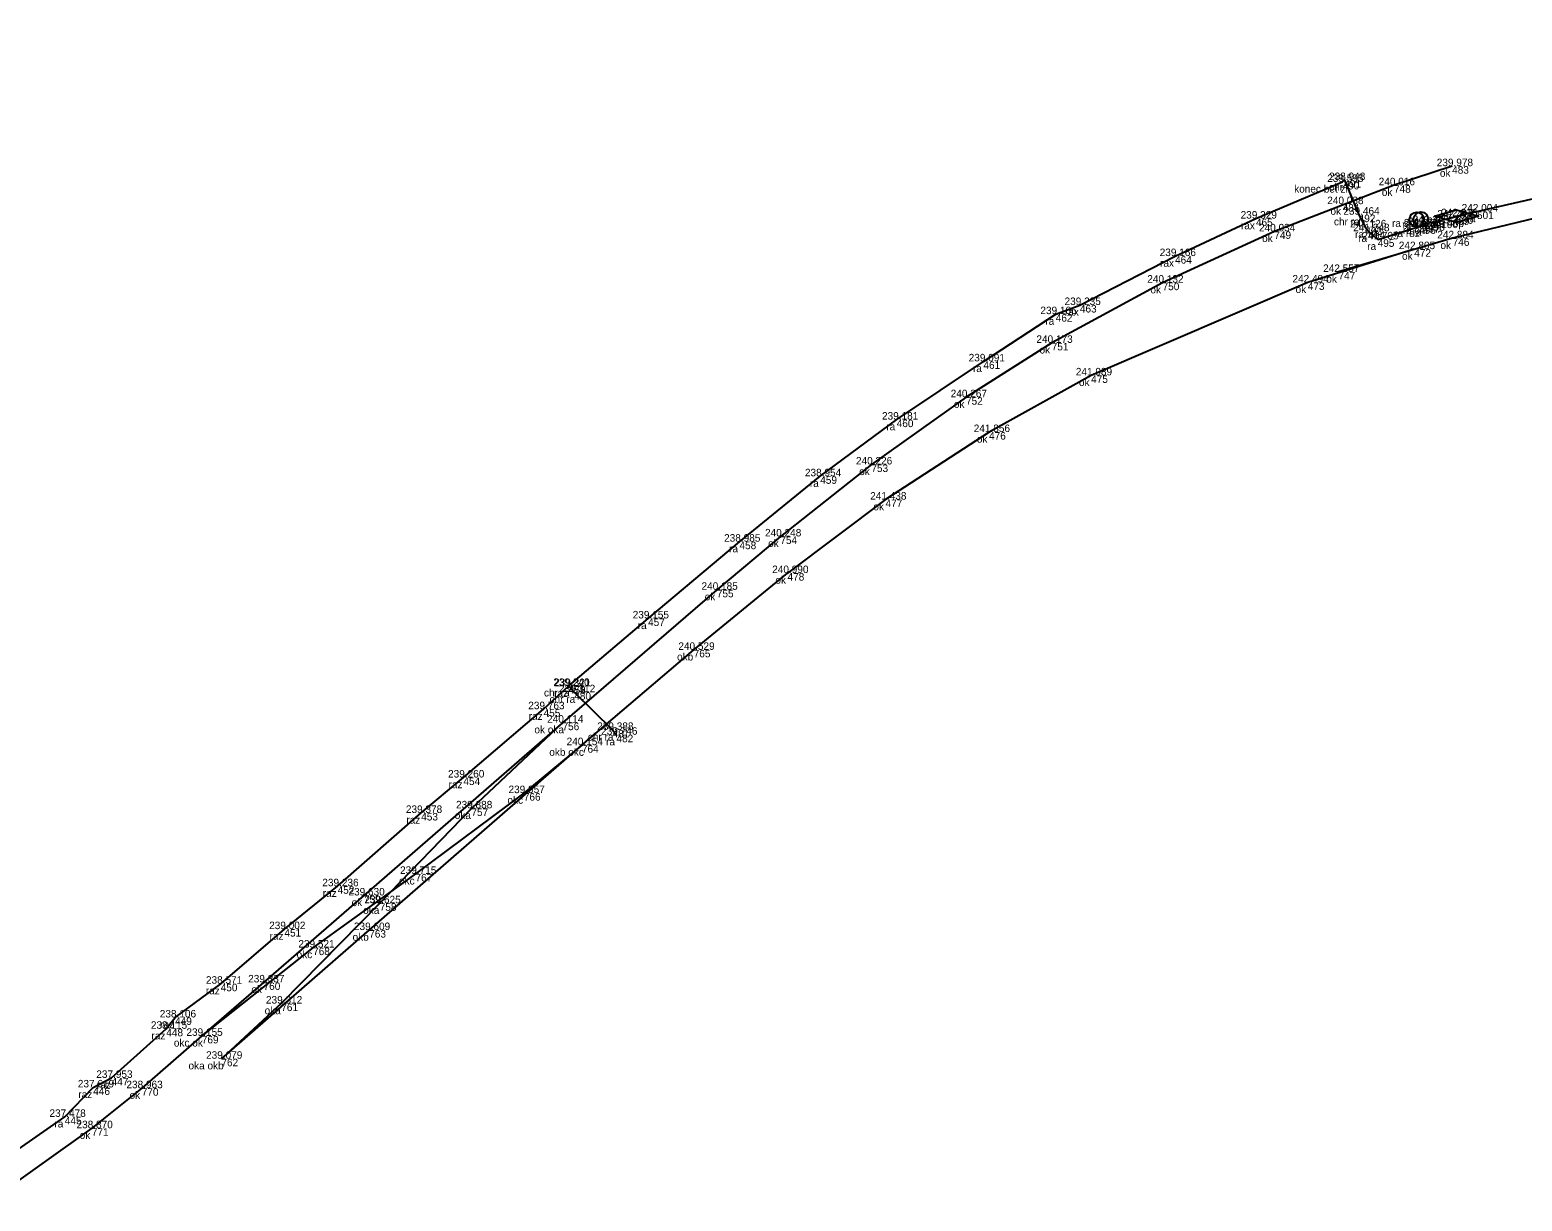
# Model space of a CAD drawing. Extents: x -759609 to -758899, y -1026011 to -1025762.
# Drawn here: x -759291 to -759052.4, y -1025950.3 to -1025763 of the extents above; entities that cross this region are included whole.
import ezdxf

# ---------------------------------------------------------------- set-up
doc = ezdxf.new("R2010")
doc.units = 0
for name, color, linetype in [('Vrstva 1', 7, 'Continuous'), ('Vrstva 28', 7, 'Continuous'), ('Vrstva 33', 7, 'Continuous'), ('Vrstva 35', 7, 'Continuous'), ('Vrstva 60', 7, 'Continuous'), ('Vrstva 61', 7, 'Continuous'), ('Vrstva 62', 7, 'Continuous')]:
    doc.layers.add(name, color=color, linetype=linetype)

msp = doc.modelspace()

# ---------------------------------------------------------------- linework, layer by layer
at = {"layer": 'Vrstva 1'}
for points in [[(-758902.55, -1025766.11), (-758912.99, -1025767.18), (-758931.03, -1025769.64), (-758951.6, -1025773.2), (-758974.19, -1025777.6), (-759000.96, -1025782.89), (-759025.45, -1025787.76), (-759044.35, -1025791.72), (-759063.54, -1025796.36), (-759081.79, -1025801.74)], [(-759063.62, -1025784.83), (-759072.91, -1025787.88), (-759092.04, -1025795.25), (-759109.9, -1025803.45), (-759127.62, -1025813.07), (-759141.32, -1025821.76), (-759156.45, -1025832.51), (-759171, -1025844.01), (-759181.15, -1025852.54), (-759205.82, -1025873.78), (-759237.58, -1025901.4), (-759253.6, -1025915.3), (-759263.47, -1025923.84), (-759273.07, -1025932.21), (-759281.05, -1025938.61), (-759297.45, -1025950.26)], [(-759069.68, -1025798.09), (-759086.69, -1025803.42), (-759121.32, -1025818.27), (-759137.64, -1025827.33), (-759154.19, -1025838.13), (-759169.85, -1025849.87)], [(-759260.34, -1025927.5), (-759236.71, -1025906.93), (-759202.71, -1025877.38), (-759184.85, -1025862.14), (-759169.85, -1025849.87)], [(-759205.82, -1025873.78), (-759220.38, -1025887.48), (-759235.03, -1025902.65), (-759250.77, -1025918.68), (-759260.34, -1025927.5)], [(-759202.71, -1025877.38), (-759212, -1025885.04), (-759229.32, -1025897.95), (-759245.68, -1025909.73), (-759263.47, -1025923.84)]]:
    msp.add_lwpolyline(points, dxfattribs=at)
at = {"layer": 'Vrstva 28'}
for points in [[(-759063.54, -1025793.03), (-759062.92, -1025792.84), (-759059.65, -1025792.08), (-759043.8, -1025788.44), (-759029.74, -1025785.63), (-759012.27, -1025782.09), (-759002.49, -1025780.17), (-759001.63, -1025779.68), (-758999.1, -1025779.52), (-758985.35, -1025776.25), (-758985.36, -1025776.26), (-758959.77, -1025770.53), (-758951.22, -1025768.17), (-758944.78, -1025766.82), (-758944.75, -1025766.82), (-758934.78, -1025765.55), (-758913.94, -1025763.04), (-758913.31, -1025763.73)], [(-759204.83, -1025867.9), (-759192.14, -1025857.12), (-759177.53, -1025844.85), (-759164.62, -1025834.4), (-759152.4, -1025825.34), (-759138.54, -1025816.03), (-759126.98, -1025808.48), (-759123.12, -1025807.02), (-759107.91, -1025799.2), (-759094.98, -1025793.21), (-759081.13, -1025787.35), (-759080.85, -1025787.05), (-759078.56, -1025792.58), (-759077.49, -1025794.61), (-759076.98, -1025795.23), (-759075.52, -1025796.53), (-759068.91, -1025794.46), (-759068.28, -1025794.23), (-759067.47, -1025793.95)], [(-759067.47, -1025793.95), (-759063.54, -1025793.03)], [(-759299.69, -1025946.77), (-759285.37, -1025936.79), (-759280.83, -1025932.08), (-759277.89, -1025930.56), (-759269.15, -1025922.71), (-759267.74, -1025920.9), (-759260.45, -1025915.51), (-759250.26, -1025906.78), (-759241.76, -1025899.93), (-759228.4, -1025888.21), (-759221.66, -1025882.55), (-759208.84, -1025871.63), (-759204.83, -1025867.9)], [(-759204.83, -1025867.9), (-759204.8, -1025867.96), (-759203.94, -1025868.92), (-759197.82, -1025874.94), (-759197.19, -1025875.71)]]:
    msp.add_lwpolyline(points, dxfattribs=at)
at = {"layer": 'Vrstva 33'}
for p, q in [((-759065.47, -1025793.13), (-759064.67, -1025792.33)), ((-759063.4, -1025793.71), (-759061.8, -1025792.15)), ((-759060.02, -1025793.02), (-759059.72, -1025792.73))]:
    msp.add_line(p, q, dxfattribs=at)
msp.add_lwpolyline([(-759066.45, -1025792.84), (-759062.92, -1025791.82), (-759059.4, -1025792.84), (-759062.92, -1025793.85)], close=True, dxfattribs=at)
for centre in [(-759069.27, -1025793.34), (-759068.62, -1025793.32)]:
    msp.add_circle(centre, 1.17, dxfattribs=at)
at = {"layer": 'Vrstva 35'}
for points in [[(-759080.85, -1025787.05), (-759078.56, -1025792.58)], [(-759067.47, -1025793.95), (-759063.54, -1025793.03)], [(-759204.8, -1025867.96), (-759203.94, -1025868.92), (-759197.82, -1025874.94)]]:
    msp.add_lwpolyline(points, dxfattribs=at)
at = {"layer": 'Vrstva 60'}
for p, q in [((-759063.62, -1025784.83), (-759063.62, -1025784.83)), ((-759081.13, -1025787.35), (-759081.13, -1025787.35)), ((-759080.85, -1025787.05), (-759080.85, -1025787.05)), ((-759072.91, -1025787.88), (-759072.91, -1025787.88)), ((-759094.98, -1025793.21), (-759094.98, -1025793.21)), ((-759081.12, -1025790.9), (-759081.12, -1025790.9)), ((-759078.56, -1025792.58), (-759078.56, -1025792.58)), ((-759063.54, -1025793.03), (-759063.54, -1025793.03)), ((-759062.92, -1025792.84), (-759062.92, -1025792.84)), ((-759059.65, -1025792.08), (-759059.65, -1025792.08)), ((-759092.04, -1025795.25), (-759092.04, -1025795.25)), ((-759077.49, -1025794.61), (-759077.49, -1025794.61)), ((-759076.98, -1025795.23), (-759076.98, -1025795.23)), ((-759068.91, -1025794.46), (-759068.91, -1025794.46)), ((-759068.28, -1025794.23), (-759068.28, -1025794.23)), ((-759067.47, -1025793.95), (-759067.47, -1025793.95)), ((-759075.52, -1025796.53), (-759075.52, -1025796.53)), ((-759063.54, -1025796.36), (-759063.54, -1025796.36)), ((-759107.91, -1025799.2), (-759107.91, -1025799.2)), ((-759069.68, -1025798.09), (-759069.68, -1025798.09)), ((-759081.79, -1025801.74), (-759081.79, -1025801.74)), ((-759109.9, -1025803.45), (-759109.9, -1025803.45)), ((-759086.69, -1025803.42), (-759086.69, -1025803.42)), ((-759123.12, -1025807.02), (-759123.12, -1025807.02)), ((-759126.98, -1025808.48), (-759126.98, -1025808.48)), ((-759127.62, -1025813.07), (-759127.62, -1025813.07)), ((-759138.54, -1025816.03), (-759138.54, -1025816.03)), ((-759121.32, -1025818.27), (-759121.32, -1025818.27)), ((-759141.32, -1025821.76), (-759141.32, -1025821.76)), ((-759152.4, -1025825.34), (-759152.4, -1025825.34)), ((-759137.64, -1025827.33), (-759137.64, -1025827.33)), ((-759156.45, -1025832.51), (-759156.45, -1025832.51)), ((-759164.62, -1025834.4), (-759164.62, -1025834.4)), ((-759154.19, -1025838.13), (-759154.19, -1025838.13)), ((-759177.53, -1025844.85), (-759177.53, -1025844.85)), ((-759171, -1025844.01), (-759171, -1025844.01)), ((-759169.85, -1025849.87), (-759169.85, -1025849.87)), ((-759181.15, -1025852.54), (-759181.15, -1025852.54)), ((-759192.14, -1025857.12), (-759192.14, -1025857.12)), ((-759184.85, -1025862.14), (-759184.85, -1025862.14)), ((-759204.83, -1025867.9), (-759204.83, -1025867.9)), ((-759204.8, -1025867.96), (-759204.8, -1025867.96)), ((-759203.94, -1025868.92), (-759203.94, -1025868.92)), ((-759208.84, -1025871.63), (-759208.84, -1025871.63)), ((-759205.82, -1025873.78), (-759205.82, -1025873.78)), ((-759197.82, -1025874.94), (-759197.82, -1025874.94)), ((-759197.19, -1025875.71), (-759197.19, -1025875.71)), ((-759202.71, -1025877.38), (-759202.71, -1025877.38)), ((-759221.66, -1025882.55), (-759221.66, -1025882.55)), ((-759212, -1025885.04), (-759212, -1025885.04)), ((-759228.4, -1025888.21), (-759228.4, -1025888.21)), ((-759220.38, -1025887.48), (-759220.38, -1025887.48)), ((-759229.32, -1025897.95), (-759229.32, -1025897.95)), ((-759241.76, -1025899.93), (-759241.76, -1025899.93)), ((-759237.58, -1025901.4), (-759237.58, -1025901.4)), ((-759235.03, -1025902.65), (-759235.03, -1025902.65)), ((-759250.26, -1025906.78), (-759250.26, -1025906.78)), ((-759236.71, -1025906.93), (-759236.71, -1025906.93)), ((-759245.68, -1025909.73), (-759245.68, -1025909.73)), ((-759260.45, -1025915.51), (-759260.45, -1025915.51)), ((-759253.6, -1025915.3), (-759253.6, -1025915.3)), ((-759250.77, -1025918.68), (-759250.77, -1025918.68)), ((-759267.74, -1025920.9), (-759267.74, -1025920.9)), ((-759269.15, -1025922.71), (-759269.15, -1025922.71)), ((-759263.47, -1025923.84), (-759263.47, -1025923.84)), ((-759260.34, -1025927.5), (-759260.34, -1025927.5)), ((-759277.89, -1025930.56), (-759277.89, -1025930.56)), ((-759280.83, -1025932.08), (-759280.83, -1025932.08)), ((-759273.07, -1025932.21), (-759273.07, -1025932.21)), ((-759285.37, -1025936.79), (-759285.37, -1025936.79)), ((-759281.05, -1025938.61), (-759281.05, -1025938.61))]:
    msp.add_line(p, q, dxfattribs=at)

# ---------------------------------------------------------------- texts
for s, p in [('483', (-759063.62, -1025786.03)), ('490', (-759081.13, -1025788.55)), ('491', (-759080.85, -1025788.25)), ('748', (-759072.91, -1025789.08)), ('465', (-759094.98, -1025794.41)), ('484', (-759081.12, -1025792.1)), ('492', (-759078.56, -1025793.78)), ('499', (-759063.54, -1025794.23)), ('500', (-759062.92, -1025794.04)), ('501', (-759059.65, -1025793.28)), ('749', (-759092.04, -1025796.45)), ('493', (-759077.49, -1025795.81)), ('494', (-759076.98, -1025796.43)), ('496', (-759068.91, -1025795.66)), ('497', (-759068.28, -1025795.43)), ('498', (-759067.47, -1025795.15)), ('495', (-759075.52, -1025797.72)), ('746', (-759063.54, -1025797.56)), ('464', (-759107.91, -1025800.4)), ('472', (-759069.68, -1025799.29)), ('747', (-759081.79, -1025802.94)), ('750', (-759109.9, -1025804.65)), ('473', (-759086.69, -1025804.61)), ('463', (-759123.12, -1025808.22)), ('462', (-759126.98, -1025809.68)), ('751', (-759127.62, -1025814.27)), ('461', (-759138.54, -1025817.23)), ('475', (-759121.32, -1025819.47)), ('752', (-759141.32, -1025822.96)), ('460', (-759152.4, -1025826.54)), ('476', (-759137.64, -1025828.53)), ('753', (-759156.45, -1025833.71)), ('459', (-759164.62, -1025835.6)), ('477', (-759154.19, -1025839.33)), ('458', (-759177.53, -1025846.05)), ('754', (-759171, -1025845.21)), ('478', (-759169.85, -1025851.07)), ('755', (-759181.15, -1025853.74)), ('457', (-759192.14, -1025858.32)), ('765', (-759184.85, -1025863.34)), ('479', (-759204.83, -1025869.09)), ('456', (-759204.8, -1025869.16)), ('480', (-759203.94, -1025870.12)), ('455', (-759208.84, -1025872.83)), ('756', (-759205.82, -1025874.98)), ('481', (-759197.82, -1025876.14)), ('482', (-759197.19, -1025876.91)), ('764', (-759202.71, -1025878.58)), ('454', (-759221.66, -1025883.75)), ('766', (-759212, -1025886.24)), ('453', (-759228.4, -1025889.41)), ('757', (-759220.38, -1025888.69)), ('767', (-759229.32, -1025899.15)), ('452', (-759241.76, -1025901.13)), ('759', (-759237.58, -1025902.6)), ('758', (-759235.03, -1025903.85)), ('451', (-759250.26, -1025907.97)), ('763', (-759236.71, -1025908.13)), ('768', (-759245.68, -1025910.93)), ('450', (-759260.45, -1025916.71)), ('760', (-759253.6, -1025916.5)), ('761', (-759250.77, -1025919.88)), ('449', (-759267.74, -1025922.09)), ('448', (-759269.15, -1025923.91)), ('769', (-759263.47, -1025925.05)), ('762', (-759260.34, -1025928.7)), ('447', (-759277.89, -1025931.76)), ('446', (-759280.83, -1025933.28)), ('770', (-759273.07, -1025933.41)), ('445', (-759285.37, -1025937.98)), ('771', (-759281.05, -1025939.81))]:
    msp.add_text(s, height=1.2, dxfattribs=at).set_placement(p)
at = {"layer": 'Vrstva 61'}
for s, p in [('239.978', (-759066.08, -1025784.83)), ('238.948', (-759083.3, -1025787.05)), ('239.595', (-759083.59, -1025787.35)), ('240.016', (-759075.36, -1025787.88)), ('240.038', (-759083.58, -1025790.9)), ('239.329', (-759097.43, -1025793.21)), ('239.464', (-759081.01, -1025792.58)), ('241.852', (-759071.35, -1025794.46)), ('242.268', (-759070.73, -1025794.23)), ('242.373', (-759069.92, -1025793.95)), ('242.414', (-759065.99, -1025793.03)), ('242.216', (-759065.38, -1025792.84)), ('242.004', (-759062.1, -1025792.08)), ('240.034', (-759094.49, -1025795.25)), ('241.126', (-759079.94, -1025794.61)), ('241.248', (-759079.43, -1025795.23)), ('241.705', (-759077.98, -1025796.53)), ('242.884', (-759065.99, -1025796.36)), ('239.166', (-759110.37, -1025799.2)), ('242.805', (-759072.14, -1025798.09)), ('240.132', (-759112.35, -1025803.45)), ('242.494', (-759089.14, -1025803.42)), ('242.557', (-759084.24, -1025801.74)), ('239.106', (-759129.43, -1025808.48)), ('239.235', (-759125.57, -1025807.02)), ('240.173', (-759130.07, -1025813.07)), ('239.091', (-759140.9, -1025816.03)), ('241.989', (-759123.77, -1025818.27)), ('240.267', (-759143.77, -1025821.76)), ('239.181', (-759154.75, -1025825.34)), ('241.856', (-759140.09, -1025827.33)), ('240.226', (-759158.91, -1025832.51)), ('238.954', (-759167.07, -1025834.4)), ('241.438', (-759156.64, -1025838.13)), ('240.248', (-759173.45, -1025844.01)), ('238.985', (-759179.99, -1025844.85)), ('240.990', (-759172.3, -1025849.87)), ('240.185', (-759183.6, -1025852.54)), ('239.155', (-759194.6, -1025857.12)), ('240.529', (-759187.3, -1025862.14)), ('239.240', (-759207.28, -1025867.9)), ('239.321', (-759207.16, -1025867.96)), ('239.312', (-759206.39, -1025868.92)), ('239.763', (-759211.29, -1025871.63)), ('240.114', (-759208.27, -1025873.78)), ('239.388', (-759200.27, -1025874.94)), ('240.154', (-759205.16, -1025877.38)), ('239.746', (-759199.64, -1025875.71)), ('239.260', (-759224.11, -1025882.55)), ('239.957', (-759214.45, -1025885.04)), ('239.378', (-759230.85, -1025888.21)), ('239.888', (-759222.84, -1025887.48)), ('239.715', (-759231.78, -1025897.95)), ('239.236', (-759244.21, -1025899.93)), ('239.630', (-759240.03, -1025901.4)), ('239.625', (-759237.48, -1025902.65)), ('239.002', (-759252.71, -1025906.78)), ('239.609', (-759239.16, -1025906.93)), ('239.521', (-759248.04, -1025909.73)), ('238.571', (-759262.81, -1025915.51)), ('239.337', (-759256.06, -1025915.3)), ('239.312', (-759253.22, -1025918.68)), ('238.115', (-759271.61, -1025922.71)), ('238.106', (-759270.19, -1025920.9)), ('239.155', (-759265.93, -1025923.84)), ('239.079', (-759262.79, -1025927.5)), ('237.619', (-759283.29, -1025932.08)), ('237.953', (-759280.34, -1025930.56)), ('238.963', (-759275.52, -1025932.21)), ('237.478', (-759287.82, -1025936.79)), ('238.870', (-759283.5, -1025938.61))]:
    msp.add_text(s, height=1.2, dxfattribs=at).set_placement(p)
at = {"layer": 'Vrstva 62'}
for s, p in [('ok', (-759065.57, -1025786.53)), ('konec bet zl', (-759088.87, -1025789.05)), ('chr', (-759083.28, -1025788.75)), ('ok', (-759074.86, -1025789.58)), ('ok', (-759083.07, -1025792.6)), ('chr ra', (-759082.51, -1025794.28)), ('ra', (-759061.31, -1025793.78)), ('rax', (-759097.38, -1025794.91)), ('ra', (-759079.15, -1025796.31)), ('ra spk stara 48p', (-759073.23, -1025794.54)), ('ra rez', (-759072.89, -1025796.16)), ('ra chr oc100', (-759071.61, -1025794.73)), ('ra chr', (-759071.5, -1025795.65)), ('ra', (-759069.94, -1025795.93)), ('ok', (-759093.99, -1025796.95)), ('ra', (-759078.64, -1025796.93)), ('ra', (-759077.19, -1025798.22)), ('ok', (-759065.49, -1025798.06)), ('rax', (-759110.31, -1025800.9)), ('ok', (-759071.63, -1025799.79)), ('ok', (-759083.73, -1025803.44)), ('ok', (-759111.85, -1025805.15)), ('ok', (-759088.64, -1025805.11)), ('ra', (-759128.64, -1025810.18)), ('rax', (-759125.52, -1025808.72)), ('ok', (-759129.57, -1025814.77)), ('ra', (-759140.21, -1025817.73)), ('ok', (-759123.27, -1025819.97)), ('ok', (-759143.26, -1025823.46)), ('ra', (-759154.06, -1025827.04)), ('ok', (-759139.59, -1025829.03)), ('ok', (-759158.4, -1025834.21)), ('ra', (-759166.28, -1025836.1)), ('ok', (-759156.13, -1025839.83)), ('ra', (-759179.19, -1025846.55)), ('ok', (-759172.95, -1025845.71)), ('ok', (-759171.79, -1025851.57)), ('ok', (-759183.09, -1025854.24)), ('ra', (-759193.8, -1025858.82)), ('okb', (-759187.51, -1025863.84)), ('chr ra', (-759208.78, -1025869.59)), ('chr ra', (-759207.89, -1025870.62)), ('raz', (-759207.18, -1025869.66)), ('raz', (-759211.22, -1025873.33)), ('ok oka', (-759210.31, -1025875.48)), ('chr ra', (-759201.77, -1025876.64)), ('ra', (-759198.85, -1025877.41)), ('okb okc', (-759207.93, -1025879.08)), ('raz', (-759224.04, -1025884.25)), ('okc', (-759214.62, -1025886.74)), ('oka', (-759223.04, -1025889.19)), ('raz', (-759230.78, -1025889.91)), ('okc', (-759231.95, -1025899.65)), ('raz', (-759244.14, -1025901.63)), ('ok', (-759239.53, -1025903.1)), ('oka', (-759237.68, -1025904.35)), ('raz', (-759252.64, -1025908.47)), ('okb', (-759239.37, -1025908.63)), ('okc', (-759248.31, -1025911.43)), ('raz', (-759262.83, -1025917.21)), ('ok', (-759255.55, -1025917)), ('oka', (-759253.43, -1025920.38)), ('raz', (-759270.12, -1025922.59)), ('raz', (-759271.53, -1025924.41)), ('okc ok', (-759267.94, -1025925.55)), ('oka okb', (-759265.6, -1025929.2)), ('raz', (-759280.27, -1025932.26)), ('raz', (-759283.21, -1025933.78)), ('ok', (-759275.02, -1025933.91)), ('ra', (-759287.03, -1025938.48)), ('ok', (-759282.99, -1025940.31))]:
    msp.add_text(s, height=1.2, dxfattribs=at).set_placement(p)

doc.saveas('drawing.dxf')
